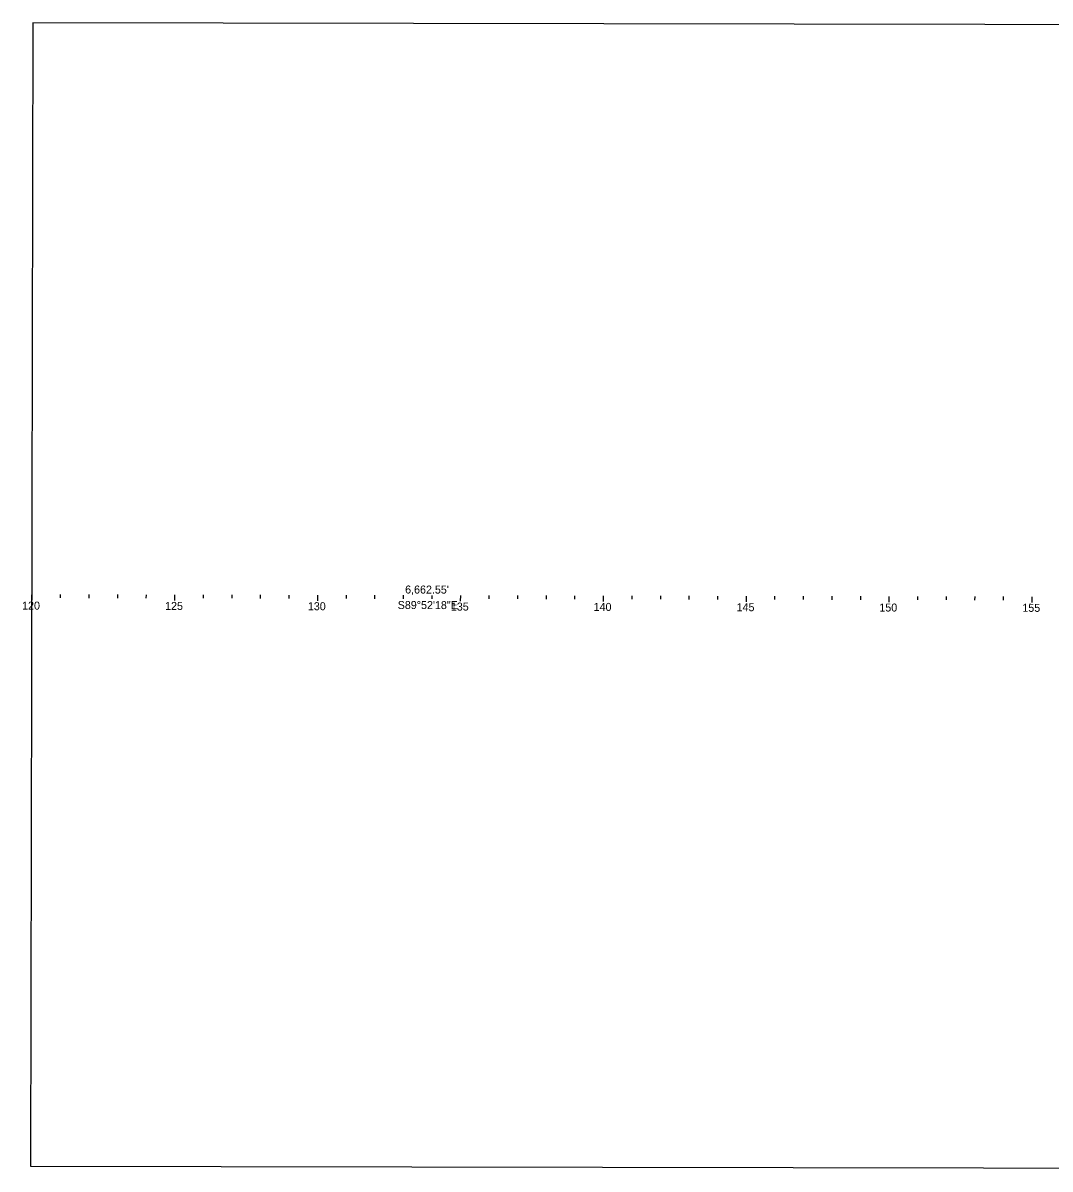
# Model space of a CAD drawing. Extents: x 117326 to 225548, y 573011 to 581051.
# Drawn here: x 129802 to 133397, y 573011 to 577021 of the extents above; entities that cross this region are included whole.
import ezdxf

# ---------------------------------------------------------------- set-up
doc = ezdxf.new("R2010")
doc.units = 0
for name, color, linetype in [('_CIVIL_CONSTRUCTION', 7, 'Continuous'), ('GE_P_Alignment_100_Cardinal_Points', 7, 'Continuous'), ('GE_P_Alignment_100_Curve_Data', 7, 'Continuous'), ('GE_P_Alignment_100_Distances', 7, 'Continuous')]:
    doc.layers.add(name, color=color, linetype=linetype)

msp = doc.modelspace()

# ---------------------------------------------------------------- linework, layer by layer
at = {"layer": 'GE_P_Alignment_100_Curve_Data'}
for p, q in [((129833, 575021.4), (129832.9, 575001.4)), ((129933, 575021.2), (129932.9, 575009.2)), ((130033, 575021), (130032.9, 575009)), ((130133, 575020.8), (130132.9, 575008.8)), ((130233, 575020.5), (130232.9, 575008.5)), ((130333, 575020.3), (130332.9, 575000.3)), ((130433, 575020.1), (130432.9, 575008.1)), ((130533, 575019.9), (130532.9, 575007.9)), ((130633, 575019.6), (130632.9, 575007.6)), ((130733, 575019.4), (130732.9, 575007.4)), ((130833, 575019.2), (130832.9, 574999.2)), ((130933, 575019), (130932.9, 575007)), ((131033, 575018.7), (131032.9, 575006.7)), ((131133, 575018.5), (131132.9, 575006.5)), ((131233, 575018.3), (131232.9, 575006.3)), ((131333, 575018.1), (131332.9, 574998.1)), ((131433, 575017.8), (131432.9, 575005.8)), ((131533, 575017.6), (131532.9, 575005.6)), ((131633, 575017.4), (131632.9, 575005.4)), ((131733, 575017.2), (131732.9, 575005.2)), ((131833, 575016.9), (131832.9, 574996.9)), ((131933, 575016.7), (131932.9, 575004.7)), ((132033, 575016.5), (132032.9, 575004.5)), ((132133, 575016.3), (132132.9, 575004.3)), ((132233, 575016), (132232.9, 575004)), ((132333, 575015.8), (132332.9, 574995.8)), ((132433, 575015.6), (132432.9, 575003.6)), ((132533, 575015.4), (132532.9, 575003.4)), ((132633, 575015.2), (132632.9, 575003.2)), ((132733, 575014.9), (132732.9, 575002.9)), ((132833, 575014.7), (132832.9, 574994.7)), ((132933, 575014.5), (132932.9, 575002.5)), ((133033, 575014.3), (133032.9, 575002.3)), ((133133, 575014), (133132.9, 575002)), ((133233, 575013.8), (133232.9, 575001.8)), ((133333, 575013.6), (133332.9, 574993.6))]:
    msp.add_line(p, q, dxfattribs=at)
at = {"layer": 'GE_P_Alignment_100_Distances'}
msp.add_lwpolyline([(129837.4, 577021.4), (129828.5, 573021.4), (135832.7, 573010.7), (135833.2, 577010.7)], close=True, dxfattribs=at)

# ---------------------------------------------------------------- texts
at = {"layer": '_CIVIL_CONSTRUCTION'}
msp.add_text('S89°52\'18"E', height=28, rotation=359.8716, dxfattribs=at).set_placement((131113.8, 574970.6))
at = {"layer": 'GE_P_Alignment_100_Cardinal_Points'}
msp.add_text("6,662.55'", height=28, rotation=359.8716, dxfattribs=at).set_placement((131139.8, 575024.7))
at = {"layer": 'GE_P_Alignment_100_Curve_Data'}
for s, p in [('120', (129799.4, 574968.5)), ('125', (130299.8, 574967.4)), ('130', (130799.4, 574966.3)), ('135', (131299.8, 574965.1)), ('140', (131799.4, 574964)), ('145', (132299.8, 574962.9)), ('150', (132799.4, 574961.8)), ('155', (133299.8, 574960.7))]:
    msp.add_text(s, height=28, rotation=359.8716, dxfattribs=at).set_placement(p)

doc.saveas('drawing.dxf')
